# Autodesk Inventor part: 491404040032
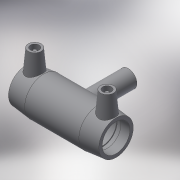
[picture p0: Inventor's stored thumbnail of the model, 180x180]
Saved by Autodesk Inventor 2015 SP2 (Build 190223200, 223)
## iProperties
Created: 2017-06
Part Number: 491404040032
Material: Generic
Description: PLASSON REDUCING TEE 40x32x40
Document SubType Name: Modeling
Designer: KIM
Mass: 57.3761 g
Surface Area: 241.06 cm^2
Volume: 57.3761 cm^3
Density: 1 g/cm^3
Appearance: Default
Author: KIM
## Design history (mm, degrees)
derived "491404.ipt"
feature "Solid1::491404.ipt"
tag "TaggingFeature1"
body "Solid1"
other parameters: "d2" = 56, "d3" = 43, "d4" = 24, "d5" = 50.4, "d6" = 38, "d8" = 168 deg, "d10" = 17.2, "d11" = 5.73333, "d14" = 17.6296, "d17" = 36, "d19" = 3.52592, "d20" = 168 deg, "d22" = 52.08, "d23" = 56, "d25" = 135 deg, "d26" = 84, "d29" = 47, "d30" = 15, "d31" = 48, "d34" = 5 deg, "d35" = 15, "d39" = 5 deg, "d41" = 4, "d42" = 14, "d43" = 0, "d45" = 4, "d46" = 6, "d47" = 0, "d48" = -75, "d49" = 32, "d51" = 0, "d52" = 25.6, "d54" = 0, "d55" = 50.4, "d56" = 56, "d57" = 42, "d58" = 135 deg, "d59" = 43, "d60" = 43, "d61" = 135 deg, "d62" = 75, "d72" = 54.6, "d73" = 27.3, "d74" = -75, "d75" = 33.6, "d77" = 0, "d78" = 25.6, "d80" = 0, "d81" = 32, "d82" = 47, "d83" = 0, "d84" = 3, "d85" = 0, "d86" = 14.33333, "d87" = 51.0384, "d88" = 5.73333, "d89" = 3, "d90" = 0, "L_1" = 43, "D_" = 56, "A_" = 47, "d_2" = 12, "H_" = 75, "d_1" = 32
